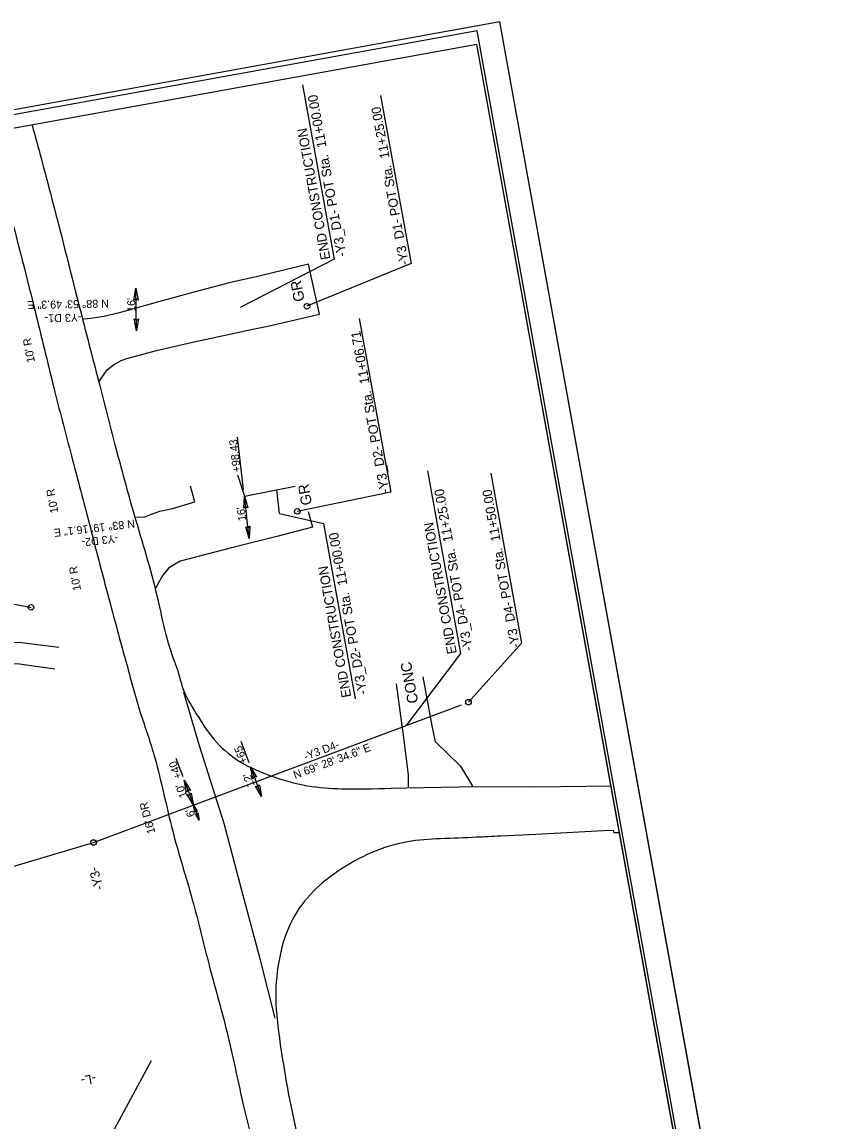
# Model space of a CAD drawing. Extents: x 1620652 to 1621205, y 897765 to 898506.
# Drawn here: x 1620905.7 to 1621204.7, y 898094.1 to 898506 of the extents above; entities that cross this region are included whole.
import ezdxf

# ---------------------------------------------------------------- set-up
doc = ezdxf.new("R2010")
doc.units = 0
for name, color, linetype in [('Exist Roads EOP', 7, 'Continuous'), ('Exist Roads EOP Other', 7, 'Continuous'), ('Exist Roads EOT', 7, 'Continuous'), ('Exist Roads Soil', 7, 'Continuous'), ('Exist Roads Soil Text', 7, 'Continuous'), ('Prop Dimension', 7, 'Continuous'), ('Prop Horizontal Alignment', 7, 'Continuous'), ('Prop Horizontal Alignment Direction Label', 7, 'Continuous'), ('Prop Horizontal Alignment Station Label', 7, 'Continuous'), ('Prop Terminator CELL', 7, 'Continuous'), ('Sheet Cutting Line CELL', 7, 'Continuous'), ('Sheet Layout Plan Border', 7, 'Continuous'), ('Sheet Plot Border Inside CELL', 7, 'Continuous'), ('Sheet Plot Border Outside CELL', 7, 'Continuous'), ('Sheet Typical CELL', 7, 'Continuous')]:
    doc.layers.add(name, color=color, linetype=linetype)

msp = doc.modelspace()

# ---------------------------------------------------------------- linework, layer by layer
at = {"layer": 'Exist Roads EOP'}
for points in [[(1620945.98, 898261.48), (1620946.15, 898260.69), (1620950, 898247.15)], [(1621043.99, 898218.8), (1621049.6, 898219.01), (1621049.67, 898218.95), (1621076, 898219.52), (1621098.08, 898219.37), (1621126.35, 898219.77)], [(1621129.55, 898202.09), (1621127.52, 898202.1), (1621127.42, 898202.86), (1621125.76, 898203.02), (1621098.22, 898201.46), (1621084.97, 898200.86)], [(1621005.9, 898102.25), (1621012.34, 898072.02), (1621016.26, 898056.83), (1621022.54, 898032.5), (1621032.42, 897993.85), (1621042.89, 897957.22), (1621054.85, 897914), (1621062.57, 897885.28)]]:
    msp.add_lwpolyline(points, dxfattribs=at)
for points in [[(1620909.49, 898467.33), (1620916.38, 898441.77), (1620927.17, 898399.44), (1620934.47, 898371.18), (1620940.55, 898347.53), (1620947.85, 898320.96), (1620956.25, 898291.01), (1620962.93, 898265.94), (1620963.32, 898264.95), (1620965.99, 898256.26), (1620971.03, 898246.7), (1620978.7, 898235.95), (1620987.66, 898228.63), (1620998.78, 898223.52), (1621012.71, 898219.77), (1621025.49, 898218.66), (1621043.99, 898218.8)], [(1620893.15, 898464.37), (1620900.36, 898437.64), (1620911.06, 898395.8), (1620918.06, 898367.23), (1620924.24, 898343.43), (1620931.2, 898316.86), (1620938.69, 898288.18), (1620945.98, 898261.48)], [(1620950, 898247.15), (1620955.45, 898230.24), (1620962.17, 898202.75), (1620969.53, 898177.07), (1620975.83, 898152.51), (1620982.98, 898125.57), (1620988.73, 898099.66), (1620997.22, 898068.12)], [(1621084.97, 898200.86), (1621075.99, 898200.43), (1621062.54, 898199.89), (1621050.08, 898198.74), (1621036.74, 898194.72), (1621023.93, 898187.58), (1621013.76, 898179.01), (1621006.28, 898168.1), (1621001.92, 898153.74), (1621000.81, 898138.72), (1621001.7, 898128.58), (1621005.9, 898102.25)]]:
    msp.add_spline(points, degree=3, dxfattribs=at)
at = {"layer": 'Exist Roads EOP Other'}
for points in [[(1621055.9, 898260.63), (1621059.26, 898242.23), (1621060.46, 898236.37), (1621070.05, 898227.14), (1621074.55, 898219.66)], [(1621050.53, 898219.3), (1621050.49, 898223.74), (1621049.47, 898231.81), (1621048.82, 898237.76), (1621046.02, 898258)]]:
    msp.add_lwpolyline(points, dxfattribs=at)
at = {"layer": 'Exist Roads EOT'}
msp.add_lwpolyline([(1621000.55, 898132.71), (1620994.98, 898154.92), (1620988.63, 898178.6), (1620981.48, 898205.63), (1620972.22, 898234.71), (1620966.35, 898254.74)], dxfattribs=at)
at = {"layer": 'Exist Roads Soil'}
for points in [[(1620934.53, 898371.17), (1620937.57, 898375.62), (1620939.96, 898377.47), (1620942.93, 898379.06), (1620944.99, 898379.92), (1620948.27, 898380.75), (1620956.13, 898382.8), (1620969.05, 898385.8), (1620979.5, 898388.07), (1620992.19, 898390.82), (1620997.79, 898391.96), (1621017.13, 898396.42), (1621013.02, 898415.27), (1620995.08, 898410.89), (1620983.31, 898408.16), (1620970.57, 898404.8)], [(1620970.57, 898404.8), (1620957.34, 898401.2), (1620942.15, 898396.97), (1620936.53, 898395.61), (1620931.49, 898394.9), (1620928.79, 898394.55)], [(1620986.42, 898336.33), (1620989.02, 898328.31), (1621008.07, 898332)], [(1620948.64, 898320.35), (1620951.7, 898320.53), (1620954.62, 898321.71), (1620957.36, 898322.68), (1620962.06, 898323.7), (1620970.45, 898326.11), (1620968.86, 898331.99)], [(1621012.91, 898322.58), (1621014.52, 898316.67)], [(1621014.52, 898316.67), (1621001.17, 898313.14), (1620985.24, 898309.11), (1620965.01, 898303.94), (1620960.7, 898301.36), (1620958.43, 898298.69), (1620956.66, 898295.37), (1620955.85, 898293.81)], [(1620919.58, 898271.57), (1620905.51, 898273.32), (1620890.18, 898273.76), (1620877.53, 898274.44), (1620862.54, 898274.26), (1620836.86, 898278.11), (1620806.8, 898281.21)], [(1620918.02, 898263.47), (1620904.84, 898265.34), (1620889.85, 898265.76), (1620877.36, 898266.43), (1620861.99, 898266.26), (1620835.87, 898270.17), (1620806.27, 898273.23)]]:
    msp.add_lwpolyline(points, dxfattribs=at)
at = {"layer": 'Prop Dimension'}
for p, q in [((1620948.67, 898390.19), (1620948.36, 898406.19)), ((1620988.74, 898330.77), (1620986.44, 898350.42)), ((1621002.19, 898321.8), (1621001.15, 898330.66)), ((1620990.88, 898312.42), (1620989.02, 898328.31)), ((1620987.69, 898236.51), (1620990.71, 898228.45)), ((1620963.39, 898230.13), (1620965.97, 898223.24)), ((1620991.29, 898226.9), (1620995.49, 898215.68)), ((1620966.48, 898221.88), (1620969.98, 898212.51)), ((1620969.98, 898212.51), (1620972.09, 898206.89))]:
    msp.add_line(p, q, dxfattribs=at)
at = {"layer": 'Prop Horizontal Alignment'}
msp.add_line((1620932.52, 898198.49), (1621070.36, 898250.09), dxfattribs=at)
at = {"layer": 'Prop Horizontal Alignment Station Label'}
for p, q in [((1621010.84, 898482.44), (1621022.67, 898417.12)), ((1621040.06, 898478.45), (1621051.47, 898415.44)), ((1621022.67, 898417.12), (1620987.46, 898398.94)), ((1621051.47, 898415.44), (1621012.46, 898399.42)), ((1621032.08, 898394.81), (1621043.86, 898329.74)), ((1621057.6, 898337.79), (1621070, 898269.26)), ((1621081.3, 898336.95), (1621092.84, 898273.19)), ((1621043.86, 898329.74), (1621008.85, 898322.58)), ((1621002.19, 898321.8), (1621018.68, 898317.97)), ((1621018.68, 898317.97), (1621030.57, 898252.33)), ((1620815.78, 898304.86), (1620909.12, 898286.61)), ((1621092.84, 898273.19), (1621073, 898251.08)), ((1621070, 898269.26), (1621049.59, 898242.31)), ((1620897.67, 898188.12), (1620932.52, 898198.49)), ((1620912.22, 898039.04), (1620954.2, 898116.85))]:
    msp.add_line(p, q, dxfattribs=at)
for centre in [(1621012.46, 898399.42), (1621008.85, 898322.58), (1620909.12, 898286.61), (1621073, 898251.08), (1620932.52, 898198.49)]:
    msp.add_circle(centre, 1.05, dxfattribs=at)
at = {"layer": 'Prop Terminator CELL'}
for points in [[(1620947.67, 898401.67), (1620948.36, 898406.19), (1620949.24, 898401.68), (1620948.43, 898402.24)], [(1620949.35, 898394.71), (1620948.67, 898390.19), (1620947.78, 898394.7), (1620948.59, 898394.14)], [(1620988.77, 898323.75), (1620989.02, 898328.31), (1620990.34, 898323.91), (1620989.48, 898324.39)], [(1620991.13, 898316.98), (1620990.88, 898312.42), (1620989.56, 898316.82), (1620990.42, 898316.34)], [(1620992.14, 898222.41), (1620991.29, 898226.9), (1620993.63, 898222.94), (1620992.68, 898223.2)], [(1620967.33, 898217.39), (1620966.48, 898221.88), (1620968.81, 898217.92), (1620967.86, 898218.18)], [(1620994.64, 898220.16), (1620995.49, 898215.68), (1620993.16, 898219.63), (1620994.11, 898219.37)], [(1620969.13, 898217), (1620969.98, 898212.51), (1620967.65, 898216.47), (1620968.6, 898216.21)], [(1620970.49, 898209.82), (1620969.98, 898212.51), (1620971.38, 898210.14), (1620970.81, 898210.29)], [(1620971.58, 898209.59), (1620972.09, 898206.89), (1620970.68, 898209.27), (1620971.26, 898209.11)]]:
    msp.add_lwpolyline(points, close=True, dxfattribs=at)
at = {"layer": 'Sheet Cutting Line CELL'}
msp.add_line((1621204.68, 897843.14), (1621084.7, 898505.97), dxfattribs=at)
at = {"layer": 'Sheet Layout Plan Border'}
msp.add_lwpolyline([(1621182.95, 897907.07), (1621076.08, 898497.49), (1620740.08, 898436.67), (1620754.33, 898357.93), (1620677.04, 898343.94), (1620769.66, 897832.26)], close=True, dxfattribs=at)
at = {"layer": 'Sheet Plot Border Inside CELL'}
msp.add_lwpolyline([(1620660.9, 898427.42), (1620779.63, 897771.48), (1621194.92, 897846.65), (1621076.19, 898502.6)], close=True, dxfattribs=at)
at = {"layer": 'Sheet Plot Border Outside CELL'}
msp.add_lwpolyline([(1620651.74, 898427.6), (1620771.72, 897764.77), (1621204.68, 897843.14), (1621084.7, 898505.97)], close=True, dxfattribs=at)
at = {"layer": 'Sheet Typical CELL'}
msp.add_lwpolyline([(1620662.79, 898422.69), (1620769.66, 897832.28), (1621182.94, 897907.09), (1621076.08, 898497.49)], close=True, dxfattribs=at)

# ---------------------------------------------------------------- texts
at = {"layer": 'Exist Roads Soil Text'}
for s, p in [('GR', (1621011.61, 898401.54)), ('GR', (1621014.4, 898325.24)), ('CONC', (1621054.21, 898250.99))]:
    msp.add_text(s, height=4, rotation=100.2583, dxfattribs=at).set_placement(p)
at = {"layer": 'Prop Dimension'}
for s, rotation, p in [("16'", 91.103, (1620948.21, 898397.35)), ("10' R", 100.2599, (1620910.59, 898378.65)), ('+98.43', 96.6789, (1620987.7, 898337.4)), ("10' R", 100.2599, (1620919.35, 898322.19)), ("16'", 96.7532, (1620989.72, 898319.16)), ("10' R", 100.2599, (1620927.86, 898293.15)), ('+65', 110.5237, (1620990.28, 898228.65)), ('+40', 110.5237, (1620965.76, 898222.95)), ("12'", 110.5237, (1620992.98, 898219.85)), ("10'", 110.5237, (1620967.73, 898215.86)), ("16' DR", 104.8686, (1620955.7, 898202.21)), ("6'", 110.5237, (1620970.66, 898208.67))]:
    msp.add_text(s, height=3, rotation=rotation, dxfattribs=at).set_placement(p)
at = {"layer": 'Prop Horizontal Alignment Direction Label'}
for s, rotation, p in [('N 88%%d 53\' 49.3" E', 181.103, (1620938.25, 898401.96)), ('-Y3 D1-', 181.103, (1620928, 898396.65)), ('N 83%%d 19\' 16.1" E', 186.6789, (1620947.83, 898319.51)), ('-Y3 D2-', 186.6789, (1620941.6, 898313.93)), ('N 69%%d 28\' 34.6" E', 20.5237, (1621008.05, 898222.24)), ('-Y3 D4-', 20.5237, (1621011.94, 898229.2))]:
    msp.add_text(s, height=3, rotation=rotation, dxfattribs=at).set_placement(p)
at = {"layer": 'Prop Horizontal Alignment Station Label'}
for s, height, rotation, p in [('-Y3_D1- POT Sta.  11+00.00', 3.584, 100.2599, (1621027.24, 898418.29)), ('-Y3_D1- POT Sta.  11+25.00', 3.5, 100.2599, (1621050.67, 898415.2)), ('END CONSTRUCTION', 3.584, 100.2599, (1621021.25, 898417.21)), ('-Y3_D2- POT Sta.  11+06.71', 3.584, 100.2599, (1621043.37, 898329.77)), ('-Y3_D4- POT Sta.  11+25.00', 3.584, 100.2599, (1621074.62, 898270.56)), ('-Y3_D4- POT Sta.  11+50.00', 3.5, 100.2599, (1621092.26, 898271.75)), ('END CONSTRUCTION', 3.584, 100.2599, (1621068.62, 898269.47)), ('-Y3_D2- POT Sta.  11+00.00', 3.584, 100.2599, (1621035.08, 898254.23)), ('END CONSTRUCTION', 3.584, 100.2599, (1621029.09, 898253.15)), ('-Y3-', 3.5, 104.8727, (1620936.31, 898181.12)), ('-L-', 3.5, 190.2599, (1620933.1, 898111.8))]:
    msp.add_text(s, height=height, rotation=rotation, dxfattribs=at).set_placement(p)

doc.saveas('drawing.dxf')
